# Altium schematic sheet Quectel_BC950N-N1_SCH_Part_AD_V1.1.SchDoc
size A4
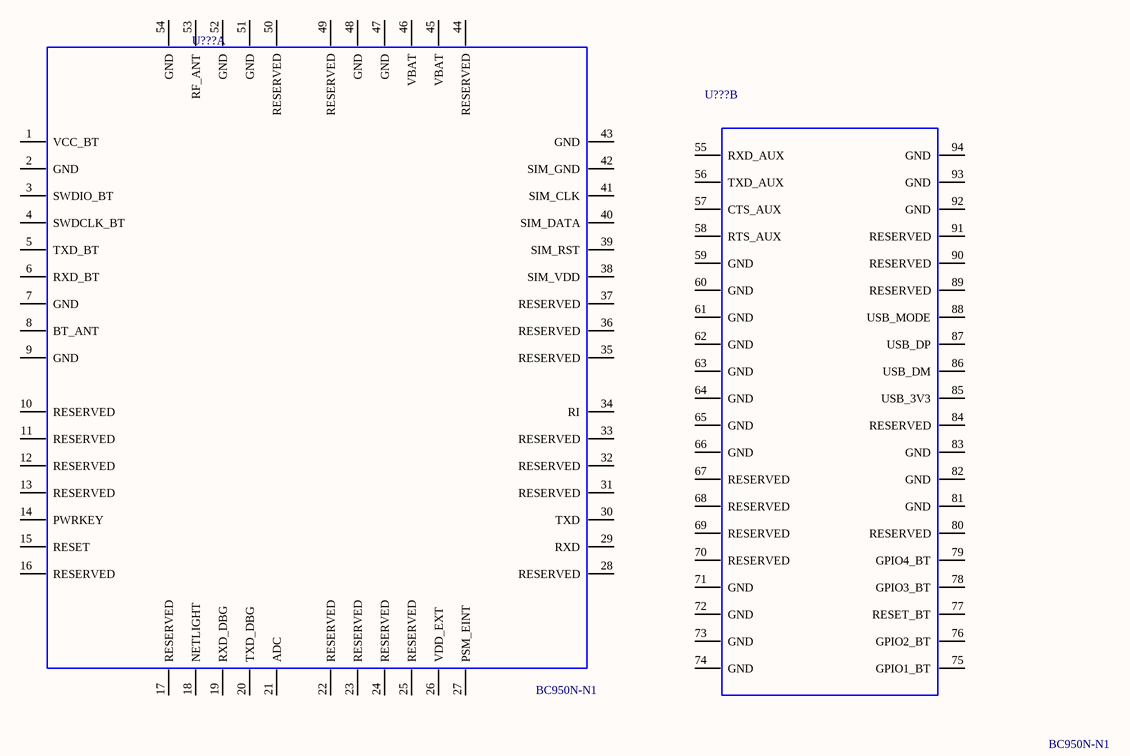
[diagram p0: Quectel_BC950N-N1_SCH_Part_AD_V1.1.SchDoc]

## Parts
(Parts that share a designator on the sheet are numbered #1, #2 ... from top to bottom, then left to right.)
U???#1  BC950N-N1  (part A of 2)
U???#2  BC950N-N1  (part B of 2)

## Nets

Not connected (* = marked no-connect by the designer): U???#1 1(VCC_BT) 2(GND) 3(SWDIO_BT) 4(SWDCLK_BT) 5(TXD_BT) 6(RXD_BT) 7(GND) 8(BT_ANT) 9(GND) 10(RESERVED) 11(RESERVED) 12(RESERVED) 13(RESERVED) 14(PWRKEY) 15(RESET) 16(RESERVED) 17(RESERVED) 18(NETLIGHT) 19(RXD_DBG) 20(TXD_DBG) 21(ADC) 22(RESERVED) 23(RESERVED) 24(RESERVED) 25(RESERVED) 26(VDD_EXT) 27(PSM_EINT) 28(RESERVED) 29(RXD) 30(TXD) 31(RESERVED) 32(RESERVED) 33(RESERVED) 34(RI) 35(RESERVED) 36(RESERVED) 37(RESERVED) 38(SIM_VDD) 39(SIM_RST) 40(SIM_DATA) 41(SIM_CLK) 42(SIM_GND) 43(GND) 44(RESERVED) 45(VBAT) 46(VBAT) 47(GND) 48(GND) 49(RESERVED) 50(RESERVED) 51(GND) 52(GND) 53(RF_ANT) 54(GND); U???#2 55(RXD_AUX) 56(TXD_AUX) 57(CTS_AUX) 58(RTS_AUX) 59(GND) 60(GND) 61(GND) 62(GND) 63(GND) 64(GND) 65(GND) 66(GND) 67(RESERVED) 68(RESERVED) 69(RESERVED) 70(RESERVED) 71(GND) 72(GND) 73(GND) 74(GND) 75(GPIO1_BT) 76(GPIO2_BT) 77(RESET_BT) 78(GPIO3_BT) 79(GPIO4_BT) 80(RESERVED) 81(GND) 82(GND) 83(GND) 84(RESERVED) 85(USB_3V3) 86(USB_DM) 87(USB_DP) 88(USB_MODE) 89(RESERVED) 90(RESERVED) 91(RESERVED) 92(GND) 93(GND) 94(GND)

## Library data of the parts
U???#1 U???#2 = BC950N-N1: Manufacturer: QCECTEL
